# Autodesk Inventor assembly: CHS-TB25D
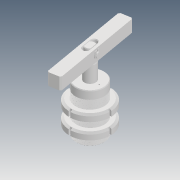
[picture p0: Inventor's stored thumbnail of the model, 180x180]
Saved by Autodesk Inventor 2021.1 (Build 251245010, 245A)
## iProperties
Created: 2019-04
Part Number: CHS-TB25D
Description: STEP AP203
Document SubType Name: Assembly
Designer: user
Title: chs-tb25d_asm.STEP
Revision Number: ÈÎºÎ
Sending System: SolidWorks 2017
Preprocessor: SwSTEP 2.0
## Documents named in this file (7)
- D:\Vault_2016\Projekty\Clamptek\Hydraulic\CHS\CHS-25\Inventor\CHS-TB25D\CHS-TB25D.iam
- D:\Vault_2016\Projekty\Clamptek\Hydraulic\CHS\CHS-25\Inventor\CHS-TB25D\CHS-TB25-03.ipt
- D:\Vault_2016\Projekty\Clamptek\Hydraulic\CHS\CHS-25\Inventor\CHS-TB25D\CHS-TB25-04.ipt
- D:\Vault_2016\Projekty\Clamptek\Hydraulic\CHS\CHS-25\Inventor\CHS-TB25D\CHS-25D-02_4.ipt
- D:\Vault_2016\Projekty\Clamptek\Hydraulic\CHS\CHS-25\Inventor\CHS-TB25D\CHS-25D-01_4.ipt
- D:\Vault_2016\Projekty\Clamptek\Hydraulic\CHS\CHS-25\Inventor\CHS-TB25D\Öá8µ²È¦.ipt
- D:\Vault_2016\Projekty\Clamptek\Hydraulic\CHS\CHS-25\Inventor\CHS-TB25D\Xiao.ipt
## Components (8 placed, 8 different names)
1. CHS-TB25-03_1
2. CHS-TB25-04_2
3. CHS-TB25-04_3
4. CHS-25D-02_4_4
5. CHS-25D-01_4_5
6. Öá8µ²È¦_6
7. Xiao_7
8. Öá8µ²È¦_8
